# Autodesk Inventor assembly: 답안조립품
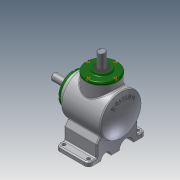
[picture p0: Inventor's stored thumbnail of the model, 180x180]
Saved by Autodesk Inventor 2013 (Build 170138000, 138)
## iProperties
Created: 2018-08
Part Number: 답안조립품
Document SubType Name: Assembly
Designer: Administrator
Author: Administrator
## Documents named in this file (14)
- C:\Users\Administrator\Desktop\480808V1001\답안조립품.iam
- C:\Users\Administrator\Desktop\480808V1001\본체.ipt
- C:\Users\Administrator\Desktop\480808V1001\메인 베벨기어.ipt
- C:\Users\Administrator\Desktop\480808V1001\메인 축.ipt
- 메인 축.ipt
- C:\Users\Administrator\Desktop\480808V1001\베어링 6203.ipt
- C:\Users\Administrator\Desktop\480808V1001\볼트 M4.ipt
- C:\Users\Administrator\Desktop\480808V1001\서브 베벨기어.ipt
- C:\Users\Administrator\Desktop\480808V1001\서브 축.ipt
- 서브 축.ipt
- C:\Users\Administrator\Desktop\480808V1001\오일실 17 32 8.ipt
- C:\Users\Administrator\Desktop\480808V1001\커버.ipt
- C:\Users\Administrator\Desktop\480808V1001\키 4x4.ipt
- C:\Users\Administrator\Desktop\480808V1001\키 5x5.ipt
